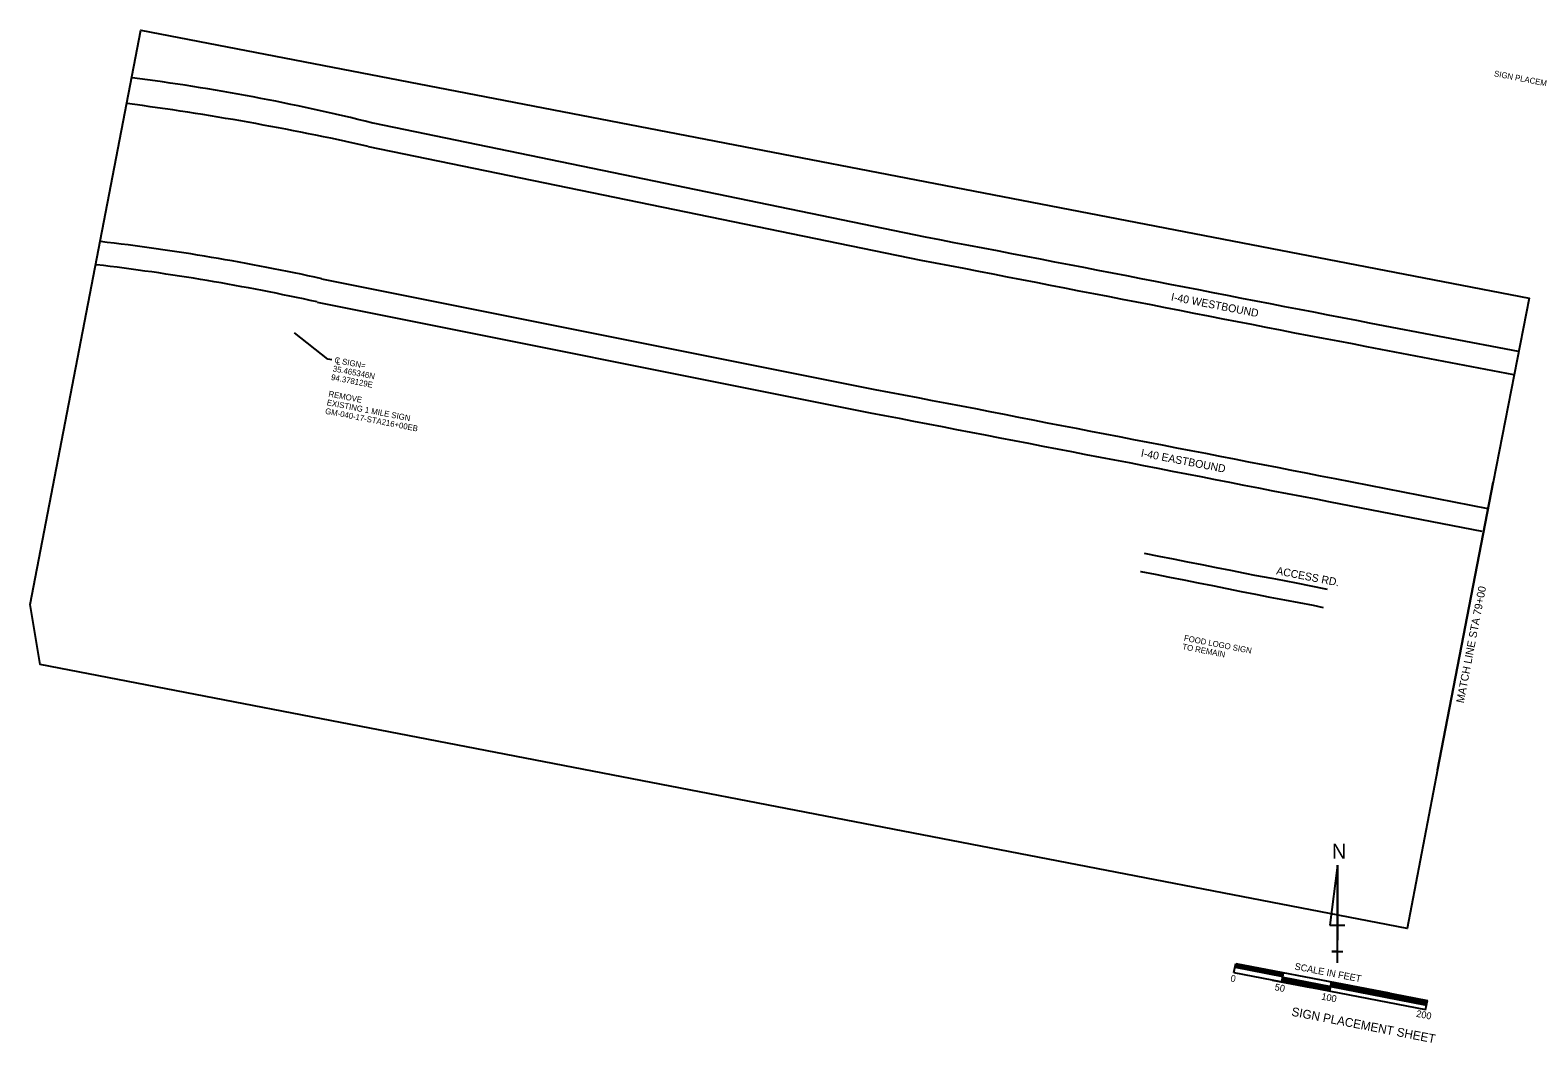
# Model space of a CAD drawing. Extents: x 604240 to 611898, y 415511 to 420909.
# Drawn here: x 604240 to 605785, y 419872 to 420909 of the extents above; entities that cross this region are included whole.
import ezdxf

# ---------------------------------------------------------------- set-up
doc = ezdxf.new("R2010")
doc.units = 0
for name, color, linetype in [('1', 7, 'Continuous'), ('5', 7, 'Continuous'), ('C-ANNO-TEXT', 7, 'Continuous'), ('G-ANNO-TEXT', 7, 'Continuous'), ('Level 1', 7, 'Continuous'), ('Level 10', 7, 'Continuous'), ('Plan Notes', 7, 'Continuous'), ('R_Annotation', 7, 'Continuous'), ('R_Draft', 7, 'Continuous')]:
    doc.layers.add(name, color=color, linetype=linetype)

msp = doc.modelspace()

# ---------------------------------------------------------------- linework, layer by layer
at = {"layer": '1'}
msp.add_lwpolyline([(604240.4, 420320.3), (604353.9, 420908.6), (605776.2, 420634.1), (605739.1, 420445.6), (605682.2, 420151), (605650.9, 419988.8), (604250.7, 420259.1)], close=True, dxfattribs=at)
at = {"layer": '5'}
msp.add_line((605682.2, 420151), (605739.1, 420445.6), dxfattribs=at)
at = {"layer": 'C-ANNO-TEXT'}
for p, q in [((604545.3, 420571.8), (604511.3, 420598.8)), ((604549.4, 420571), (604545.3, 420571.8))]:
    msp.add_line(p, q, dxfattribs=at)
at = {"layer": 'Level 1'}
for p, q in [((605579.6, 420053.6), (605571.9, 419992.1)), ((605579.6, 419953.6), (605579.6, 420053.6)), ((605579.6, 420053.6), (605579.6, 419976.7)), ((605571.9, 419992.1), (605587.2, 419992.1)), ((605579.6, 419965.2), (605573.8, 419965.2)), ((605573.8, 419965.2), (605585.3, 419965.2)), ((605579.6, 419953.6), (605579.6, 419976.7)), ((605579.6, 419953.6), (605579.6, 419965.2))]:
    msp.add_line(p, q, dxfattribs=at)
at = {"layer": 'Level 10'}
for p, q in [((605473.6, 419943.5), (605475.4, 419952.9)), ((605474.7, 419949), (605523.8, 419939.5)), ((605474.8, 419949.8), (605523.9, 419940.3)), ((605475, 419950.5), (605524.1, 419941.1)), ((605475.1, 419951.3), (605524.2, 419941.8)), ((605475.3, 419952.1), (605524.4, 419942.6)), ((605475.4, 419952.9), (605632.5, 419922.6)), ((605475.4, 419952.9), (605514.7, 419945.3)), ((605473.6, 419943.5), (605670, 419905.6)), ((605512.9, 419935.9), (605552.2, 419928.3)), ((605522.7, 419934), (605524.5, 419943.4)), ((605522.9, 419934.8), (605572, 419925.3)), ((605523, 419935.6), (605572.1, 419926.1)), ((605523.2, 419936.4), (605572.3, 419926.9)), ((605523.3, 419937.1), (605572.4, 419927.7)), ((605523.5, 419937.9), (605572.6, 419928.4)), ((605523.6, 419938.7), (605572.7, 419929.2)), ((605554, 419937.7), (605671.8, 419915)), ((605571.8, 419924.5), (605573.6, 419933.9)), ((605573.3, 419932.4), (605671.5, 419913.4)), ((605573.5, 419933.2), (605671.7, 419914.2)), ((605572.7, 419929.2), (605631.6, 419917.9)), ((605572.7, 419929.2), (605670.9, 419910.3)), ((605572.9, 419930), (605671.1, 419911.1)), ((605573, 419930.8), (605671.2, 419911.9)), ((605573.2, 419931.6), (605671.4, 419912.6)), ((605670, 419905.5), (605671.8, 419915))]:
    msp.add_line(p, q, dxfattribs=at)
at = {"layer": 'R_Draft'}
for p, q in [((604591.3, 420813.6), (605157.4, 420697)), ((604586.7, 420789.6), (605152.8, 420673.1)), ((604539, 420654), (605105.6, 420540.6)), ((604534.5, 420630.2), (605101, 420516.8))]:
    msp.add_line(p, q, dxfattribs=at)
for points in [[(605157.4, 420697), (605172.1, 420694.1), (605186.8, 420691.3), (605201.6, 420688.5), (605216.3, 420685.6), (605231, 420682.8), (605245.8, 420679.9), (605260.5, 420677.1), (605275.2, 420674.3), (605289.9, 420671.4), (605304.7, 420668.6), (605319.4, 420665.8), (605334.1, 420662.9), (605348.9, 420660.1), (605363.6, 420657.2), (605378.3, 420654.4), (605393, 420651.5), (605407.8, 420648.6), (605422.5, 420645.8), (605437.2, 420642.9), (605451.9, 420640), (605466.7, 420637.2), (605481.4, 420634.3), (605496.1, 420631.4), (605510.8, 420628.6), (605525.5, 420625.7), (605540.3, 420622.8), (605555, 420620), (605569.7, 420617.2), (605584.5, 420614.3), (605599.2, 420611.5), (605613.9, 420608.7), (605764.8, 420579.8)], [(605152.8, 420673.1), (605167.6, 420670.4), (605182.3, 420667.5), (605197, 420664.7), (605211.8, 420661.8), (605226.5, 420659), (605241.2, 420656.1), (605255.9, 420653.2), (605270.7, 420650.4), (605285.4, 420647.5), (605300.1, 420644.7), (605314.8, 420641.8), (605329.6, 420639), (605344.3, 420636.1), (605359, 420633.2), (605373.7, 420630.4), (605388.4, 420627.5), (605403.2, 420624.6), (605417.9, 420621.7), (605432.6, 420618.8), (605447.3, 420615.9), (605462.1, 420613.1), (605476.8, 420610.2), (605491.5, 420607.4), (605506.2, 420604.5), (605521, 420601.7), (605535.7, 420598.8), (605550.4, 420596), (605565.1, 420593.2), (605579.9, 420590.4), (605594.6, 420587.6), (605609.4, 420584.8), (605760.1, 420556)], [(605105.6, 420540.6), (605120.4, 420538), (605135.1, 420535.2), (605149.8, 420532.3), (605164.6, 420529.5), (605179.3, 420526.6), (605194, 420523.8), (605208.7, 420521), (605223.5, 420518.1), (605238.2, 420515.2), (605252.9, 420512.4), (605267.6, 420509.5), (605282.4, 420506.6), (605297.1, 420503.8), (605311.8, 420500.9), (605326.5, 420498.1), (605341.3, 420495.2), (605356, 420492.4), (605370.7, 420489.5), (605385.5, 420486.7), (605400.2, 420483.9), (605414.9, 420481), (605429.6, 420478.1), (605444.4, 420475.3), (605459.1, 420472.4), (605473.8, 420469.6), (605488.5, 420466.7), (605503.3, 420463.8), (605518, 420461), (605532.7, 420458.1), (605547.4, 420455.2), (605562.1, 420452.3), (605576.9, 420449.4), (605733.8, 420418.7)], [(605101, 420516.8), (605115.7, 420513.9), (605130.5, 420511.1), (605145.2, 420508.3), (605159.9, 420505.4), (605174.7, 420502.6), (605189.4, 420499.8), (605204.1, 420496.9), (605218.8, 420494.1), (605233.6, 420491.2), (605248.3, 420488.4), (605263, 420485.6), (605277.8, 420482.7), (605292.5, 420479.9), (605307.2, 420477.1), (605321.9, 420474.2), (605336.7, 420471.4), (605351.4, 420468.5), (605366.1, 420465.7), (605380.9, 420462.9), (605395.6, 420460), (605410.3, 420457.1), (605425, 420454.2), (605439.7, 420451.4), (605454.5, 420448.5), (605469.2, 420445.6), (605483.9, 420442.7), (605498.6, 420439.9), (605513.4, 420437), (605528.1, 420434.2), (605542.8, 420431.3), (605557.5, 420428.5), (605572.3, 420425.6), (605727.6, 420395.5)], [(605381.7, 420373.1), (605396.5, 420370.1), (605411.2, 420367.2), (605425.9, 420364.2), (605440.6, 420361.3), (605455.3, 420358.4), (605470, 420355.5), (605484.7, 420352.6), (605494.8, 420350.6), (605512.5, 420347.5), (605516.2, 420346.7), (605537.2, 420342.5), (605552.4, 420339.6), (605567.5, 420336.6), (605569.1, 420336.3)], [(605378, 420354.4), (605378.1, 420354.4), (605392.8, 420351.5), (605407.5, 420348.5), (605422.2, 420345.7), (605436.9, 420342.8), (605451.6, 420339.9), (605466.3, 420336.9), (605481.1, 420333.9), (605495.8, 420330.9), (605510.5, 420328.1), (605525.3, 420325.3), (605540, 420322.5), (605554.7, 420319.6), (605564.9, 420317.5)]]:
    msp.add_lwpolyline(points, dxfattribs=at)
for centre, radius, start, end in [((604059.5, 418666.3), 2212.1, 76.089, 82.5833), ((603973.7, 418052.6), 2804.8, 77.3747, 82.4989), ((604047.8, 418424.6), 2282.9, 77.5741, 83.3471), ((604038.4, 418375.9), 2308.3, 77.5914, 83.2866)]:
    msp.add_arc(centre, radius, start, end, dxfattribs=at)

# ---------------------------------------------------------------- texts
at = {"layer": 'G-ANNO-TEXT'}
for height, p in [(6, (605739.7, 420861.5)), (9, (605532, 419899.4))]:
    msp.add_text('SIGN PLACEMENT SHEET', height=height, rotation=349.0745, dxfattribs=at).set_placement(p)
at = {"layer": 'Level 1'}
msp.add_text('N', height=15.4, rotation=360, dxfattribs=at).set_placement((605573.9, 420060))
at = {"layer": 'Level 10'}
for s, height, p in [('SCALE IN FEET', 7.001, (605535.3, 419946.7)), ('0', 7, (605469.6, 419934.5)), ('50', 7, (605514.9, 419925.5)), ('100', 7, (605562.7, 419915.9)), ('200', 7, (605659.9, 419898.3))]:
    msp.add_text(s, height=height, rotation=349.0748, dxfattribs=at).set_placement(p)
at = {"layer": 'Plan Notes'}
msp.add_text('MATCH LINE STA 79+00', height=8, rotation=79.0745, dxfattribs=at).set_placement((605709, 420219))
at = {"layer": 'R_Annotation'}
for s, height, p in [('I-40 WESTBOUND', 8, (605408.7, 420631.9)), ('C SIGN=', 6, (604551.7, 420568.1)), ('L', 6, (604553.7, 420566.5)), ('94.378129E', 6, (604548.3, 420550.5)), ('35.465346N', 6, (604550, 420559.3)), ('REMOVE', 6, (604545.6, 420533.5)), ('GM-040-17-STA216+00EB', 6, (604542.2, 420515.8)), ('EXISTING 1 MILE SIGN', 6, (604543.9, 420524.6)), ('I-40 EASTBOUND', 8, (605377.8, 420472)), ('ACCESS RD.', 8, (605516.5, 420351.4)), ('FOOD LOGO SIGN', 6, (605422, 420283.4)), ('TO REMAIN', 6, (605420.3, 420274.6))]:
    msp.add_text(s, height=height, rotation=349.0745, dxfattribs=at).set_placement(p)

doc.saveas('drawing.dxf')
